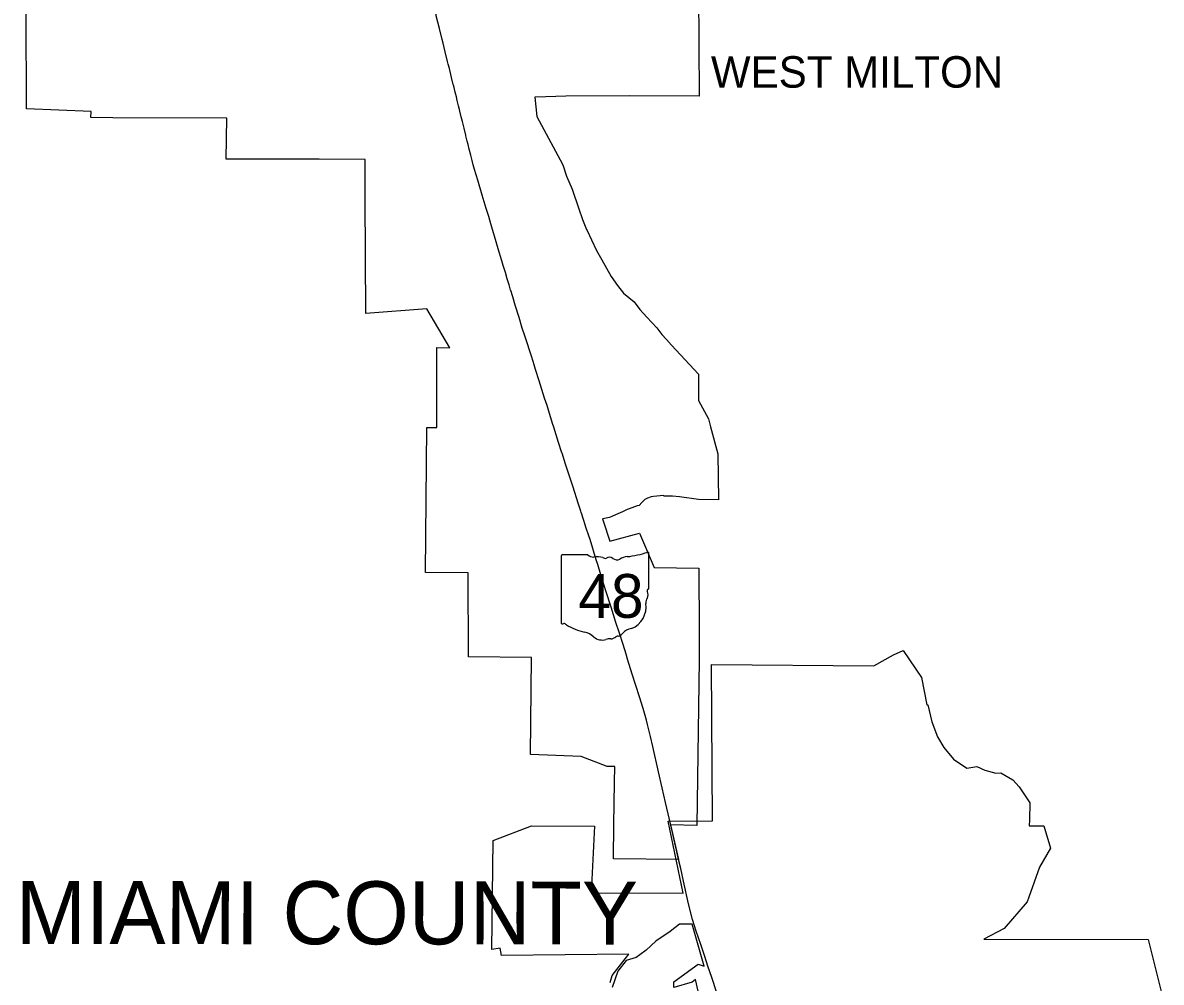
# Model space of a CAD drawing. Extents: x 0 to 34, y 0 to 22.
# Drawn here: x 4.6031 to 4.8937, y 16.1285 to 16.3735 of the extents above; entities that cross this region are included whole.
import ezdxf

# ---------------------------------------------------------------- set-up
doc = ezdxf.new("R2010")
doc.units = 0
for name, color, linetype in [('GM_X_Corporation', 7, 'Continuous'), ('GM_X_Corporation_Text', 7, 'Continuous'), ('GM_X_County_Text', 7, 'Continuous'), ('GM_X_State_Location', 7, 'Continuous'), ('GM_X_State_Route', 7, 'Continuous'), ('GM_X_State_Shield', 7, 'Continuous')]:
    doc.layers.add(name, color=color, linetype=linetype)

msp = doc.modelspace()

# ---------------------------------------------------------------- linework, layer by layer
at = {"layer": 'GM_X_Corporation'}
for points in [[(4.775590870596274, 16.38137353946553), (4.775716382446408, 16.354781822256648), (4.757928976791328, 16.35481504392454), (4.741658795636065, 16.354777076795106), (4.736555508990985, 16.354596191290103), (4.733749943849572, 16.354473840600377), (4.73430683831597, 16.34951716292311), (4.740836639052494, 16.337365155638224), (4.740981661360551, 16.336936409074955), (4.7418576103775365, 16.33435180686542), (4.743307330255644, 16.331014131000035), (4.745009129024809, 16.32599258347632), (4.745976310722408, 16.323282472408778), (4.746993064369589, 16.320667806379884), (4.747112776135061, 16.320425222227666), (4.748223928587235, 16.318064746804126), (4.749519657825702, 16.315335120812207), (4.75090398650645, 16.31297148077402), (4.753223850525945, 16.30873992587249), (4.754840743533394, 16.30644590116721), (4.756385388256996, 16.3044930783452), (4.759139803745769, 16.302201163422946), (4.7605937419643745, 16.300277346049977), (4.762401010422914, 16.29830342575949), (4.764899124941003, 16.295575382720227), (4.766169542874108, 16.293872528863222), (4.767371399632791, 16.29258629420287), (4.76869508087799, 16.29116979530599), (4.7755370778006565, 16.28377934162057), (4.775535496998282, 16.280673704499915), (4.775533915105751, 16.277038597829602), (4.778092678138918, 16.272372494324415), (4.778650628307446, 16.27030997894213), (4.780522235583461, 16.263390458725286), (4.7806319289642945, 16.251724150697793), (4.775522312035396, 16.251808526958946), (4.770665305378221, 16.252420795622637), (4.768937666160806, 16.252638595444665), (4.766685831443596, 16.252587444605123), (4.766641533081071, 16.252788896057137), (4.765763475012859, 16.252718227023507), (4.764063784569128, 16.252550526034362), (4.763452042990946, 16.252489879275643), (4.762489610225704, 16.252072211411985), (4.761845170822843, 16.251802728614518), (4.761236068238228, 16.251169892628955), (4.761116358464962, 16.25104543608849), (4.760378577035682, 16.250278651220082), (4.759921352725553, 16.250123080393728), (4.758508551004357, 16.24964212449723), (4.757606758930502, 16.249332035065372), (4.757313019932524, 16.249198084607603), (4.756142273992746, 16.248664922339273), (4.754969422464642, 16.248137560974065), (4.7536214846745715, 16.24753161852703), (4.752792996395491, 16.24715930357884), (4.752413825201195, 16.247087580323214), (4.751140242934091, 16.24684763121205), (4.751080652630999, 16.24683655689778), (4.751232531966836, 16.246363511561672), (4.752909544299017, 16.241128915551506), (4.760491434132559, 16.24318879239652), (4.764214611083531, 16.23438922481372), (4.775603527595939, 16.23424578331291), (4.775685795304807, 16.21800144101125), (4.775719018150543, 16.210809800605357), (4.7751489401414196, 16.16855752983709), (4.768440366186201, 16.16867197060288), (4.770433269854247, 16.159874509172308), (4.753880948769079, 16.160004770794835), (4.753961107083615, 16.168755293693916), (4.754144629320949, 16.179528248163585), (4.7541994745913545, 16.18358313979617), (4.752252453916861, 16.18360053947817), (4.745605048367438, 16.186198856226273), (4.732670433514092, 16.186651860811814), (4.732958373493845, 16.2114015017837), (4.71681475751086, 16.211638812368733), (4.716714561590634, 16.23306238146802), (4.705876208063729, 16.233137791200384), (4.706231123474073, 16.270187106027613), (4.708784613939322, 16.270160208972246), (4.708785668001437, 16.290577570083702), (4.712072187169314, 16.290529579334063), (4.7061736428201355, 16.300469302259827), (4.69060696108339, 16.299283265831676), (4.690476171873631, 16.328673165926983), (4.690481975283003, 16.33856648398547), (4.678727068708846, 16.33862027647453), (4.654953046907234, 16.338633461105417), (4.6551809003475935, 16.34909914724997), (4.655071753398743, 16.34909915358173), (4.626076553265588, 16.349235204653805), (4.620463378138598, 16.349324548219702), (4.620491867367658, 16.35079504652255), (4.603991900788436, 16.351526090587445), (4.603972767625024, 16.357658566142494), (4.603934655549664, 16.36987136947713), (4.603905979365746, 16.379062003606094)], [(4.752967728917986, 16.12847011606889), (4.753525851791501, 16.13028402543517), (4.756804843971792, 16.13453973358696), (4.75778156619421, 16.13572575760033), (4.725270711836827, 16.135307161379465), (4.724921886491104, 16.137260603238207), (4.722828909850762, 16.136842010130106), (4.7231079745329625, 16.164748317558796), (4.732944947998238, 16.16844590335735), (4.748991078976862, 16.16837613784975), (4.748153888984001, 16.15135328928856), (4.771595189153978, 16.15128352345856), (4.767827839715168, 16.169631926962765), (4.77912989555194, 16.169701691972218), (4.778850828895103, 16.209607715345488), (4.820291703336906, 16.209328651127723), (4.825314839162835, 16.21211928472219), (4.827826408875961, 16.213235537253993), (4.832470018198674, 16.206293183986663), (4.833810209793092, 16.199377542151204), (4.834067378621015, 16.19935960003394), (4.835150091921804, 16.194996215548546), (4.8365723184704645, 16.191207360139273), (4.838170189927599, 16.18845935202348), (4.840665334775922, 16.185490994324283), (4.84408587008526, 16.183208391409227), (4.846562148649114, 16.183598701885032), (4.848665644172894, 16.18263044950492), (4.851419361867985, 16.181884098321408), (4.852691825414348, 16.181965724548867), (4.8557853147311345, 16.180217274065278), (4.857449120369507, 16.17837382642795), (4.860163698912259, 16.17434937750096), (4.860012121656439, 16.170011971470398), (4.859928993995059, 16.168467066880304), (4.863721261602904, 16.168431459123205), (4.865377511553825, 16.162739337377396), (4.862569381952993, 16.157864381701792), (4.859836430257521, 16.15026347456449), (4.859414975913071, 16.149091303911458), (4.853575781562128, 16.142240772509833), (4.848398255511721, 16.139481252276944), (4.890356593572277, 16.139438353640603), (4.893673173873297, 16.126121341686)], [(4.77550053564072, 16.126232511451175), (4.774804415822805, 16.12923754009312), (4.773897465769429, 16.128539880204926), (4.7692929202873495, 16.127214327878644), (4.769292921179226, 16.128609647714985), (4.775432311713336, 16.133144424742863), (4.777036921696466, 16.132656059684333), (4.773967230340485, 16.143330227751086), (4.770688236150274, 16.143330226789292), (4.768316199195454, 16.141446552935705), (4.764688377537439, 16.139004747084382), (4.762176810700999, 16.136702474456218), (4.760561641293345, 16.13552383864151), (4.759595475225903, 16.134818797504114), (4.75708390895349, 16.13405137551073), (4.754990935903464, 16.13133051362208), (4.753525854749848, 16.127144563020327)]]:
    msp.add_lwpolyline(points, dxfattribs=at)
at = {"layer": 'GM_X_State_Route'}
for points in [[(4.712953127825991, 16.357722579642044), (4.712505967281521, 16.359540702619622), (4.7119459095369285, 16.3618268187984), (4.711663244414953, 16.362902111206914), (4.711476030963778, 16.363616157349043), (4.710870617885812, 16.366082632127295), (4.710334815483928, 16.368318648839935), (4.710112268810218, 16.369234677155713), (4.709426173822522, 16.37206450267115), (4.708607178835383, 16.37525926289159), (4.708548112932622, 16.375492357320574), (4.708060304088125, 16.377431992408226), (4.707953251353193, 16.377861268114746), (4.707798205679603, 16.37856160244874)], [(4.722013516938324, 16.323983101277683), (4.721360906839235, 16.326053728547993), (4.720330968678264, 16.329450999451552), (4.71921032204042, 16.33330970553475), (4.718787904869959, 16.334696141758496), (4.718370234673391, 16.33606570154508), (4.718044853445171, 16.3372264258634), (4.717737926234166, 16.338351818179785), (4.717585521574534, 16.338978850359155), (4.717405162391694, 16.339720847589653), (4.717041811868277, 16.341215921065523), (4.716743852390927, 16.34239985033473), (4.716529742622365, 16.343247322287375), (4.716192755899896, 16.344586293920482), (4.716136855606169, 16.344832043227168), (4.715731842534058, 16.3466103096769), (4.715293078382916, 16.34831685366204), (4.714990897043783, 16.349492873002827), (4.714628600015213, 16.350933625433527), (4.714521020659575, 16.35136342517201), (4.71428845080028, 16.352303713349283), (4.713963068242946, 16.353620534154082), (4.71373050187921, 16.35456345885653), (4.71344098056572, 16.35574000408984), (4.7131372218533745, 16.356976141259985), (4.712993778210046, 16.357557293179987), (4.712953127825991, 16.357722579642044)], [(4.727591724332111, 16.305250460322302), (4.7271887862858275, 16.306570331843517), (4.726881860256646, 16.307577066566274), (4.726723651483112, 16.30807647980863), (4.726246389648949, 16.309691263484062), (4.725708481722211, 16.311472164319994), (4.725344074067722, 16.31267718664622), (4.724444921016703, 16.315775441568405), (4.723932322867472, 16.317543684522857), (4.722804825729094, 16.32128531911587), (4.722553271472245, 16.322177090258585), (4.7223006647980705, 16.323072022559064), (4.722013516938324, 16.323983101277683)], [(4.7467009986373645, 16.24505967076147), (4.746101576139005, 16.24695361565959), (4.745743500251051, 16.248037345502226), (4.745616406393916, 16.248422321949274), (4.745490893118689, 16.248804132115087), (4.744890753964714, 16.250621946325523), (4.743444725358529, 16.255176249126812), (4.741628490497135, 16.260823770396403), (4.740716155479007, 16.263642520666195), (4.740694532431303, 16.263708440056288), (4.7398428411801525, 16.266341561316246), (4.739208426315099, 16.268300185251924), (4.738604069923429, 16.270227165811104), (4.738294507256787, 16.27121491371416), (4.737065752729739, 16.27517276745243), (4.7368790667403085, 16.275748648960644), (4.736252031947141, 16.27768459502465), (4.734896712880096, 16.282040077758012), (4.7339664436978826, 16.284940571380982), (4.733585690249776, 16.286138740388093), (4.73331726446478, 16.286984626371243), (4.732881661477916, 16.288355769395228), (4.732482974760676, 16.289602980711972), (4.7317884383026, 16.29177149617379), (4.731215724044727, 16.293562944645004), (4.73057761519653, 16.295557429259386), (4.729728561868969, 16.298223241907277), (4.72877984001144, 16.30135841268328), (4.72812010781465, 16.303517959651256), (4.727615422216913, 16.3051728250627), (4.727591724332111, 16.305250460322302)], [(4.768460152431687, 16.16862661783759), (4.7671549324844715, 16.1744402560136), (4.766269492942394, 16.178190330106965), (4.765320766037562, 16.18228318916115), (4.763875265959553, 16.188743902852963), (4.7632788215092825, 16.191292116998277), (4.762564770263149, 16.19430124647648), (4.76228474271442, 16.195412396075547), (4.761950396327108, 16.19662322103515), (4.761417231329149, 16.19844842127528), (4.760522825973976, 16.201412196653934), (4.758643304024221, 16.207213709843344), (4.757444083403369, 16.211026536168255), (4.757045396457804, 16.21229273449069), (4.756284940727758, 16.214758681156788), (4.7553436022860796, 16.21764018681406), (4.754441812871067, 16.220401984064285), (4.753221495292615, 16.22430920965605), (4.75192049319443, 16.22847484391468), (4.750637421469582, 16.2325503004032), (4.749842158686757, 16.235143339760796), (4.74952626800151, 16.236101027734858), (4.748956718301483, 16.23803486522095), (4.748396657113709, 16.239860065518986), (4.747771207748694, 16.24177755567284), (4.7476235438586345, 16.242228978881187), (4.7467259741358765, 16.24498075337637), (4.7467009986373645, 16.24505967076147)], [(4.770453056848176, 16.15982915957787), (4.770100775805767, 16.16144657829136), (4.769041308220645, 16.16600720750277), (4.768460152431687, 16.16862661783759)], [(4.774049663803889, 16.144513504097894), (4.773037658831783, 16.148534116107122), (4.771736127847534, 16.154299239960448), (4.771013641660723, 16.15756097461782), (4.770453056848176, 16.15982915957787)], [(4.7771368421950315, 16.135127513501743), (4.776977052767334, 16.13561268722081), (4.776128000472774, 16.138134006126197), (4.7749351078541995, 16.14158559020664), (4.774049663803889, 16.144513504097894)], [(4.780176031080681, 16.12603473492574), (4.778928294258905, 16.129770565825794), (4.777948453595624, 16.132663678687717), (4.7771368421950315, 16.135127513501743)]]:
    msp.add_lwpolyline(points, dxfattribs=at)
at = {"layer": 'GM_X_State_Shield'}
for p, q in [((4.7404892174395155, 16.237340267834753), (4.7404892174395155, 16.220355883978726)), ((4.747262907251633, 16.237632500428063), (4.740709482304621, 16.237632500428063)), ((4.762866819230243, 16.229168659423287), (4.762866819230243, 16.238053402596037)), ((4.762864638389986, 16.229170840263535), (4.762866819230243, 16.229168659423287))]:
    msp.add_line(p, q, dxfattribs=at)
for centre, radius, start, end in [((4.740745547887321, 16.237376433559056), 0.0002592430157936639, 98.1301027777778, 188.13010277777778), ((4.748823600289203, 16.23960421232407), 0.0025145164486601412, 231.61950555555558, 271.11188333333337), ((4.7496573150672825, 16.228097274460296), 0.009027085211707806, 80.48669166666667, 94.98826944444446), ((4.757922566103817, 16.232444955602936), 0.004774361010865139, 97.34618055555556, 120.7688527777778), ((4.754895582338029, 16.260788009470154), 0.02373123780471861, 275.8444694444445, 288.9064527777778), ((4.762618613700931, 16.23809025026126), 0.000249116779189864, 351.8620861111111, 97.738), ((4.7517066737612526, 16.237464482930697), 0.0007254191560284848, 219.79206111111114, 297.1023694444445), ((4.752771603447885, 16.235501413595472), 0.0015082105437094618, 54.466683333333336, 119.14113055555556), ((4.754718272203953, 16.238193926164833), 0.0018143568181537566, 233.85620555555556, 294.82819166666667), ((4.7628092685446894, 16.228516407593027), 0.00038552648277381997, 107.94398333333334, 210.33696666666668), ((4.760356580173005, 16.227393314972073), 0.002314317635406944, 340.0329638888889, 23.649566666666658), ((4.762601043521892, 16.229134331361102), 0.0002666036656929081, 289.6038111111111, 7.734130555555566), ((4.763759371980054, 16.225450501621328), 0.001683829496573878, 136.80649722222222, 186.92959444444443), ((4.756224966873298, 16.224320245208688), 0.005935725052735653, 292.3088861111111, 8.985838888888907), ((4.740747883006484, 16.220318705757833), 0.00026154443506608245, 171.9583861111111, 258.30661388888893), ((4.740787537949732, 16.222056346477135), 0.0019959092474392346, 267.33899444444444, 280.6038555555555), ((4.741195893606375, 16.219376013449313), 0.000719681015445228, 29.748380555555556, 93.27174722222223), ((4.750282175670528, 16.234635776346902), 0.017137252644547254, 240.41292222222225, 257.1985), ((4.745172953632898, 16.212725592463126), 0.0053619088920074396, 47.184155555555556, 75.83597222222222), ((4.753186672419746, 16.21801983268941), 0.0018128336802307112, 268.7770194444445, 315.54927222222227), ((4.754826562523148, 16.216374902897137), 0.0005103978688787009, 65.75173055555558, 132.64842222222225), ((4.7546089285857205, 16.218709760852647), 0.0019176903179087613, 282.8731916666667, 323.27711111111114), ((4.758727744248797, 16.215587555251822), 0.0032508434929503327, 94.40312222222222, 142.57675), ((4.750972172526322, 16.219291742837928), 0.003402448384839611, 230.70037222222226, 286.29183611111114), ((4.752938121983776, 16.213419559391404), 0.0027957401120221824, 85.69512222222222, 111.20994722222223)]:
    msp.add_arc(centre, radius, start, end, dxfattribs=at)

# ---------------------------------------------------------------- texts
at = {"layer": 'GM_X_Corporation_Text'}
msp.add_text('WEST MILTON', height=0.008037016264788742, rotation=1.0000000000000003e-05, dxfattribs=at).set_placement((4.778706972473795, 16.35691886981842))
at = {"layer": 'GM_X_County_Text'}
msp.add_text('MIAMI COUNTY', height=0.016074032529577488, rotation=359.945778, dxfattribs=at).set_placement((4.601288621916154, 16.138293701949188))
at = {"layer": 'GM_X_State_Location'}
msp.add_text('48', height=1.6074032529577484e-05, rotation=1.0000000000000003e-05, dxfattribs=at).set_placement((4.747378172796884, 16.22654940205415))
for s, p in [('s', (4.751426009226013, 16.227718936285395)), ('r', (4.751425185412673, 16.227718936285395))]:
    msp.add_text(s, height=1.6074032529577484e-05, dxfattribs=at).set_placement(p)
at = {"layer": 'GM_X_State_Shield'}
msp.add_text('48', height=0.011189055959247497, dxfattribs=at).set_placement((4.744878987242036, 16.221553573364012))

doc.saveas('drawing.dxf')
